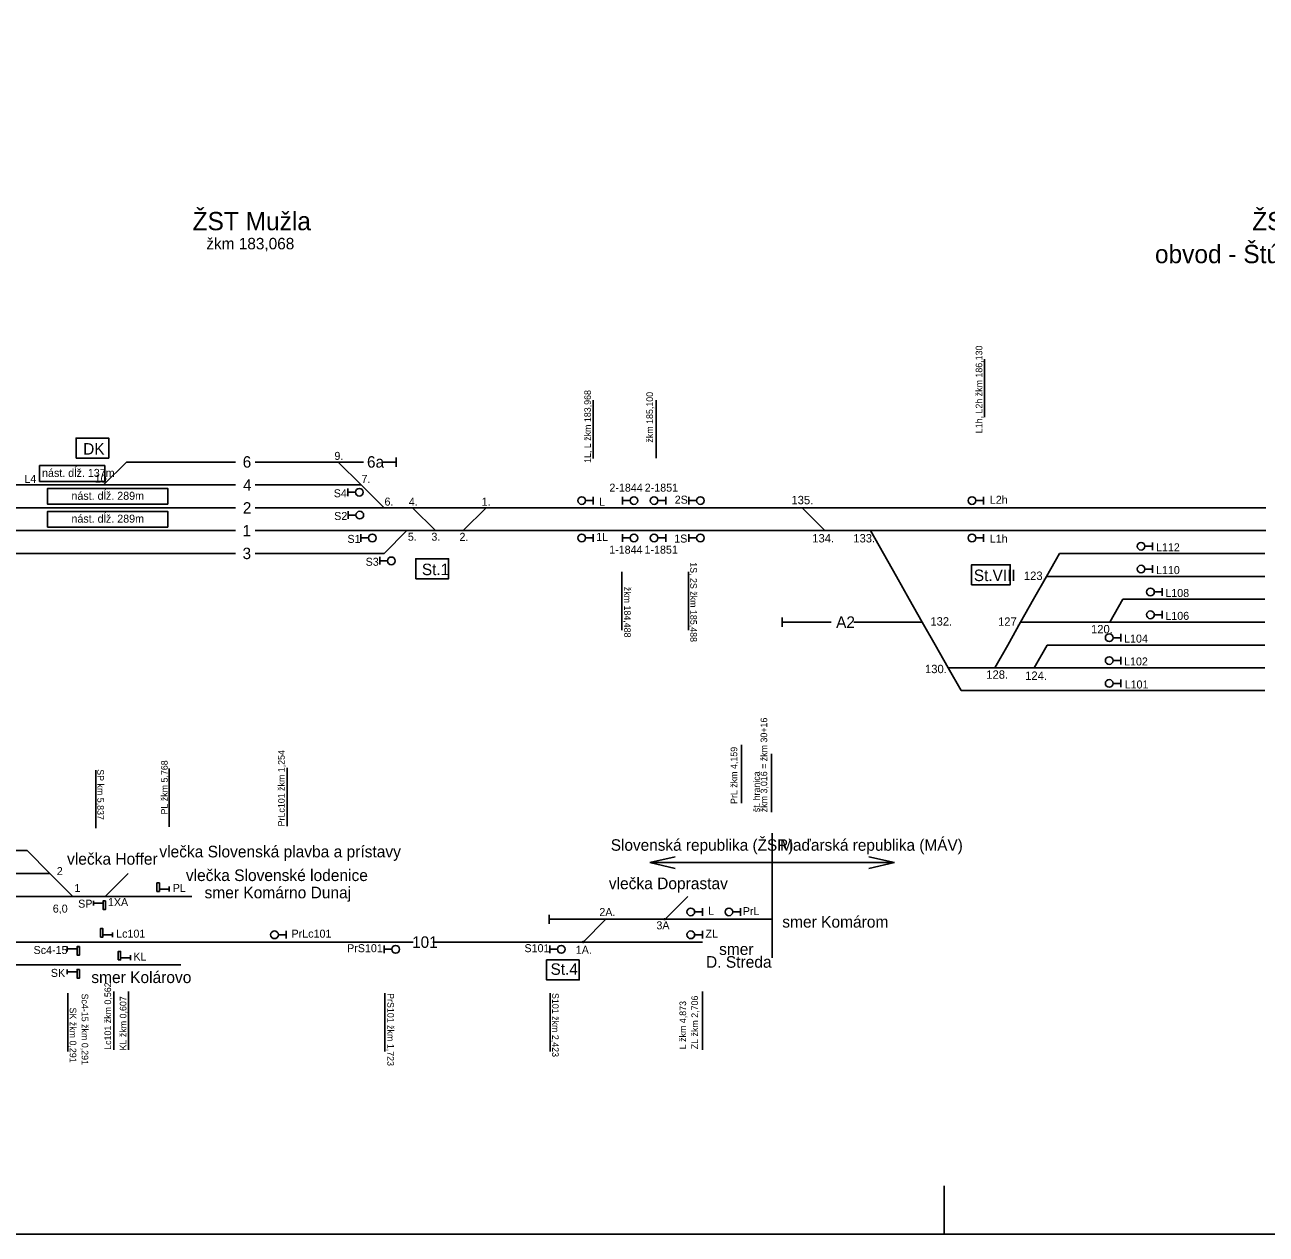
# Model space of a CAD drawing. Extents: x -119 to 851, y -238 to 59.
# Drawn here: x 390.6 to 499.2, y -238 to -132.3 of the extents above; entities that cross this region are included whole.
import ezdxf

# ---------------------------------------------------------------- set-up
doc = ezdxf.new("R2010")
doc.units = 0
for name, color, linetype in [('2', 7, 'Continuous'), ('budova', 7, 'Continuous'), ('Default', 7, 'Continuous'), ('Level 2', 7, 'Continuous'), ('nastupistia', 7, 'Continuous'), ('netlač', 7, 'Continuous'), ('popisky navestidla', 7, 'Continuous'), ('popisky stanic a zastavok', 7, 'Continuous'), ('PU_navestidla', 7, 'Continuous'), ('PU_oznacenie navestidiel', 7, 'Continuous'), ('PU_stan_kolaje', 7, 'Continuous'), ('PU_vlecky', 7, 'Continuous'), ('schema_km0-1_0-2', 7, 'Continuous'), ('schema_km1-0', 7, 'Continuous'), ('statna hranica', 7, 'Continuous')]:
    doc.layers.add(name, color=color, linetype=linetype)

msp = doc.modelspace()

# ---------------------------------------------------------------- linework, layer by layer
at = {"layer": '2'}
for p, q in [((402.64, -207.83), (403.26, -207.83)), ((403.26, -207.62), (403.26, -207.83)), ((403.26, -207.83), (403.26, -208.04)), ((396.63, -209.07), (396.63, -208.86)), ((396.63, -209.28), (396.63, -209.07)), ((397.25, -209.07), (396.63, -209.07)), ((398.31, -211.62), (398.31, -211.83)), ((397.69, -211.83), (398.31, -211.83)), ((398.31, -211.83), (398.31, -212.04)), ((394.35, -213.06), (394.35, -212.85)), ((394.98, -213.06), (394.35, -213.06)), ((394.35, -213.28), (394.35, -213.06)), ((399.25, -213.83), (399.87, -213.83)), ((399.87, -213.62), (399.87, -213.83)), ((399.87, -213.83), (399.87, -214.04)), ((394.35, -215.06), (394.35, -214.85)), ((394.35, -215.27), (394.35, -215.06)), ((394.98, -215.06), (394.35, -215.06))]:
    msp.add_line(p, q, dxfattribs=at)
for points in [[(402.19, -208.03), (402.4, -208.03), (402.4, -207.29), (402.19, -207.29)], [(402.19, -208.03), (402.4, -208.03), (402.4, -207.29), (402.19, -207.29)], [(397.69, -208.86), (397.48, -208.86), (397.48, -209.61), (397.69, -209.61)], [(397.69, -208.87), (397.48, -208.87), (397.48, -209.61), (397.69, -209.61)], [(397.25, -212.03), (397.46, -212.03), (397.46, -211.29), (397.25, -211.29)], [(397.25, -212.03), (397.46, -212.03), (397.46, -211.29), (397.25, -211.29)], [(395.42, -212.86), (395.21, -212.86), (395.21, -213.61), (395.42, -213.61)], [(395.42, -212.87), (395.21, -212.87), (395.21, -213.61), (395.42, -213.61)], [(398.8, -214.03), (399.01, -214.03), (399.01, -213.29), (398.8, -213.29)], [(398.8, -214.03), (399.01, -214.03), (399.01, -213.29), (398.8, -213.29)], [(395.42, -214.86), (395.21, -214.86), (395.21, -215.61), (395.42, -215.61)], [(395.42, -214.87), (395.21, -214.87), (395.21, -215.61), (395.42, -215.61)]]:
    msp.add_lwpolyline(points, close=True, dxfattribs=at)
at = {"layer": 'budova'}
for points in [[(395.11, -170.14), (397.98, -170.14), (397.98, -168.39), (395.11, -168.39)], [(424.82, -180.7), (427.69, -180.7), (427.69, -178.95), (424.82, -178.95)], [(473.44, -181.22), (476.82, -181.22), (476.82, -179.47), (473.44, -179.47)], [(439.12, -214.02), (436.26, -214.02), (436.26, -215.77), (439.12, -215.77)]]:
    msp.add_lwpolyline(points, close=True, dxfattribs=at)
at = {"layer": 'Default'}
for p, q in [((445.29, -205.52), (447.51, -205.01)), ((466.68, -205.52), (464.46, -205.01)), ((455.99, -205.52), (445.29, -205.52)), ((445.29, -205.52), (447.51, -206.02)), ((455.99, -205.52), (466.68, -205.52)), ((466.68, -205.52), (464.46, -206.02)), ((402.19, -208.03), (402.19, -207.29)), ((402.4, -207.29), (402.4, -208.03)), ((397.48, -209.61), (397.48, -208.86)), ((397.69, -208.86), (397.69, -209.61)), ((397.69, -209.61), (397.48, -209.61)), ((397.25, -212.03), (397.25, -211.29)), ((397.46, -211.29), (397.46, -212.03)), ((395.21, -213.61), (395.21, -212.86)), ((395.42, -213.61), (395.21, -213.61)), ((395.42, -212.86), (395.42, -213.61)), ((398.8, -214.03), (398.8, -213.29)), ((398.8, -213.29), (399.01, -213.29)), ((399.01, -213.29), (399.01, -214.03)), ((395.21, -215.61), (395.21, -214.86)), ((395.42, -214.86), (395.42, -215.61)), ((395.42, -215.61), (395.21, -215.61))]:
    msp.add_line(p, q, dxfattribs=at)
for points in [[(402.64, -207.83), (402.4, -207.83)], [(397.25, -209.07), (397.48, -209.07)], [(397.69, -211.83), (397.46, -211.83)], [(394.98, -213.06), (395.21, -213.06)], [(399.25, -213.83), (399.01, -213.83)], [(394.98, -215.06), (395.21, -215.06)]]:
    msp.add_lwpolyline(points, dxfattribs=at)
at = {"layer": 'Level 2'}
for p, q in [((423.12, -170.9), (423.12, -170.1)), ((409.05, -170.5), (399.52, -170.5)), ((418.05, -170.5), (410.78, -170.5)), ((420.25, -170.5), (418.05, -170.5)), ((423.12, -170.5), (421.98, -170.5)), ((388.2, -172.49), (409.05, -172.49)), ((410.78, -172.49), (420.05, -172.49)), ((377.88, -174.49), (394.08, -174.49)), ((394.08, -174.49), (409.05, -174.49)), ((410.78, -174.49), (417.67, -174.49)), ((417.67, -174.49), (440.34, -174.49)), ((371.76, -176.49), (392.88, -176.49)), ((392.88, -176.49), (409.05, -176.49)), ((410.78, -176.49), (418.67, -176.49)), ((418.67, -176.49), (436.97, -176.49)), ((436.97, -176.49), (440.34, -176.49)), ((388.73, -178.49), (409.05, -178.49)), ((410.78, -178.49), (422.05, -178.49)), ((456.87, -184.89), (456.87, -184.09)), ((390.83, -204.47), (386.03, -204.47)), ((392.83, -206.47), (386.03, -206.47)), ((405.25, -208.47), (362.23, -208.47)), ((436.5, -210.07), (436.5, -210.87)), ((436.5, -210.47), (441.46, -210.47)), ((449.89, -210.47), (441.46, -210.47)), ((424.6, -212.46), (387.27, -212.46)), ((449.89, -212.46), (426.32, -212.46)), ((404.28, -214.46), (386.78, -214.46))]:
    msp.add_line(p, q, dxfattribs=at)
for points in [[(490.07, -182.49), (490.47, -182.49)], [(456.87, -184.49), (461.14, -184.49)], [(463.14, -184.49), (469.12, -184.49)]]:
    msp.add_lwpolyline(points, dxfattribs=at)
at = {"layer": 'nastupistia'}
for points in [[(397.62, -172.18), (391.92, -172.18), (391.92, -170.8), (397.62, -170.8)], [(403.14, -174.18), (392.63, -174.18), (392.63, -172.8), (403.14, -172.8)], [(403.14, -176.18), (392.63, -176.18), (392.63, -174.8), (403.14, -174.8)]]:
    msp.add_lwpolyline(points, close=True, dxfattribs=at)
at = {"layer": 'netlač'}
for p, q in [((448.71, -174.49), (440.34, -174.49)), ((448.71, -174.49), (499.17, -174.49)), ((448.71, -176.49), (440.34, -176.49)), ((499.17, -176.49), (448.71, -176.49)), ((481.11, -178.49), (499.07, -178.49)), ((479.98, -180.49), (499.07, -180.49)), ((486.65, -182.49), (499.07, -182.49)), ((477.72, -184.49), (499.07, -184.49)), ((480.03, -186.49), (499.07, -186.49)), ((471.38, -188.48), (499.07, -188.48)), ((472.51, -190.48), (499.07, -190.48)), ((449.89, -210.47), (455.99, -210.47))]:
    msp.add_line(p, q, dxfattribs=at)
at = {"layer": 'popisky navestidla'}
for p, q in [((474.57, -161.48), (474.57, -166.57)), ((440.34, -170.18), (440.34, -165.09)), ((445.85, -165.07), (445.85, -170.16)), ((442.86, -180.09), (442.86, -185.18)), ((448.68, -180.09), (448.68, -185.18)), ((453.31, -195.23), (453.31, -200.32)), ((455.93, -196.01), (455.93, -201.1)), ((396.83, -202.51), (396.83, -197.42)), ((403.27, -197.29), (403.27, -202.38)), ((413.58, -197.23), (413.58, -202.32)), ((394.4, -222.03), (394.4, -216.94)), ((398.42, -216.79), (398.42, -221.88)), ((399.71, -216.79), (399.71, -221.88)), ((422.11, -222.03), (422.11, -216.94)), ((436.57, -222.03), (436.57, -216.94)), ((449.89, -221.89), (449.89, -216.8)), ((471.05, -238.01), (471.05, -233.77))]:
    msp.add_line(p, q, dxfattribs=at)
msp.add_lwpolyline([(-118.95, -238.01), (851.05, -238.01), (851.05, 58.99), (-118.95, 58.99)], close=True, dxfattribs=at)
at = {"layer": 'PU_navestidla'}
for p, q in [((418.88, -173.47), (418.88, -172.79)), ((418.88, -173.13), (419.56, -173.13)), ((440.34, -173.52), (440.34, -174.19)), ((442.89, -173.52), (442.89, -174.19)), ((446.68, -173.52), (446.68, -174.19)), ((448.71, -173.52), (448.71, -174.19)), ((474.48, -173.52), (474.48, -174.19)), ((440.34, -173.86), (439.67, -173.86)), ((442.89, -173.86), (443.56, -173.86)), ((446.68, -173.86), (446.01, -173.86)), ((448.71, -173.86), (449.38, -173.86)), ((474.48, -173.86), (473.81, -173.86)), ((418.92, -175.47), (418.92, -174.79)), ((418.92, -175.13), (419.59, -175.13)), ((420.02, -177.46), (420.02, -176.79)), ((440.34, -177.46), (440.34, -176.79)), ((442.89, -177.46), (442.89, -176.79)), ((446.68, -177.46), (446.68, -176.79)), ((448.71, -177.46), (448.71, -176.79)), ((474.48, -177.46), (474.48, -176.79)), ((420.02, -177.13), (420.7, -177.13)), ((440.34, -177.13), (439.67, -177.13)), ((442.89, -177.13), (443.56, -177.13)), ((446.68, -177.13), (446.01, -177.13)), ((448.71, -177.13), (449.38, -177.13)), ((474.48, -177.13), (473.81, -177.13)), ((489.27, -177.85), (488.6, -177.85)), ((489.27, -177.52), (489.27, -178.19)), ((421.68, -179.46), (421.68, -178.79)), ((421.68, -179.13), (422.35, -179.13)), ((489.27, -179.85), (488.6, -179.85)), ((489.27, -179.52), (489.27, -180.19)), ((490.09, -181.85), (489.41, -181.85)), ((490.09, -181.51), (490.09, -182.19)), ((490.09, -183.85), (489.41, -183.85)), ((490.09, -183.51), (490.09, -184.18)), ((486.48, -185.51), (486.48, -186.18)), ((486.48, -185.85), (485.8, -185.85)), ((486.48, -187.51), (486.48, -188.18)), ((486.48, -187.85), (485.8, -187.85)), ((486.48, -189.85), (485.8, -189.85)), ((486.48, -189.51), (486.48, -190.18)), ((449.89, -209.49), (449.89, -210.17)), ((453.22, -209.49), (453.22, -210.17)), ((449.89, -209.83), (449.22, -209.83)), ((453.22, -209.83), (452.54, -209.83)), ((413.48, -211.49), (413.48, -212.16)), ((449.89, -211.49), (449.89, -212.16)), ((413.48, -211.83), (412.81, -211.83)), ((422.06, -213.44), (422.06, -212.76)), ((436.54, -213.44), (436.54, -212.76)), ((449.89, -211.83), (449.22, -211.83)), ((422.06, -213.1), (422.73, -213.1)), ((436.54, -213.1), (437.21, -213.1))]:
    msp.add_line(p, q, dxfattribs=at)
for centre in [(419.89, -173.13), (439.34, -173.86), (443.9, -173.86), (445.67, -173.86), (449.72, -173.86), (473.47, -173.86), (419.93, -175.13), (421.03, -177.13), (439.34, -177.13), (443.9, -177.13), (445.67, -177.13), (449.72, -177.13), (473.47, -177.13), (488.26, -177.85), (422.69, -179.13), (488.26, -179.85), (489.08, -181.85), (489.08, -183.85), (485.47, -185.85), (485.47, -187.85), (485.47, -189.85), (448.88, -209.83), (452.21, -209.83), (412.47, -211.83), (448.88, -211.83), (423.07, -213.1), (437.55, -213.1)]:
    msp.add_circle(centre, 0.336, dxfattribs=at)
at = {"layer": 'PU_stan_kolaje'}
for points in [[(399.52, -170.5), (397.52, -172.49)], [(418.05, -170.5), (420.05, -172.49)], [(420.05, -172.49), (422.05, -174.49)], [(424.54, -174.49), (426.54, -176.49)], [(430.98, -174.49), (428.98, -176.49)], [(458.61, -174.49), (460.61, -176.49)], [(424.05, -176.49), (422.05, -178.49)], [(464.6, -176.49), (465.73, -178.49)], [(465.73, -178.49), (466.86, -180.49)], [(479.98, -180.49), (481.11, -178.49)], [(466.86, -180.49), (467.99, -182.49)], [(478.85, -182.49), (479.98, -180.49)], [(467.99, -182.49), (469.12, -184.49)], [(477.72, -184.49), (478.85, -182.49)], [(485.52, -184.49), (486.65, -182.49)], [(469.12, -184.49), (470.25, -186.48)], [(476.59, -186.49), (477.72, -184.49)], [(470.25, -186.48), (471.38, -188.48)], [(475.46, -188.48), (476.59, -186.49)], [(478.9, -188.48), (480.03, -186.49)], [(471.38, -188.48), (472.51, -190.48)], [(392.83, -206.47), (390.83, -204.47)], [(394.83, -208.47), (392.83, -206.47)], [(397.67, -208.47), (399.67, -206.47)], [(446.63, -210.47), (448.63, -208.47)], [(439.46, -212.46), (441.46, -210.47)]]:
    msp.add_lwpolyline(points, dxfattribs=at)
at = {"layer": 'schema_km0-1_0-2'}
for centre in [(446.58, -210.47), (439.46, -212.46)]:
    msp.add_circle(centre, 0.0502, dxfattribs=at)
at = {"layer": 'statna hranica'}
msp.add_line((455.99, -213.83), (455.99, -202.95), dxfattribs=at)

# ---------------------------------------------------------------- texts
at = {"layer": 'budova'}
for s, p in [('DK', (395.74, -169.84)), ('St.1', (425.36, -180.38)), ('St.VIII', (473.63, -180.9)), ('St.4', (436.61, -215.33))]:
    msp.add_text(s, height=1.004, dxfattribs=at).set_placement(p)
at = {"layer": 'Default'}
for s, p in [('Slovenská republika (ŽSR)', (441.88, -204.48)), ('Maďarská republika (MÁV)', (456.69, -204.48))]:
    msp.add_text(s, height=1.0044, dxfattribs=at).set_placement(p)
at = {"layer": 'Level 2'}
for s, height, p in [('135.', 0.733, (457.68, -174.18)), ('134.', 0.733, (459.5, -177.52)), ('133.', 0.733, (463.09, -177.52)), ('123.', 0.733, (478.01, -180.8)), ('A2', 1.004, (461.59, -184.99)), ('132.', 0.733, (469.83, -184.79)), ('127.', 0.733, (475.75, -184.81)), ('120.', 0.733, (483.88, -185.47)), ('130.', 0.733, (469.36, -188.95)), ('128.', 0.733, (474.72, -189.44)), ('124.', 0.733, (478.12, -189.54))]:
    msp.add_text(s, height=height, dxfattribs=at).set_placement(p)
at = {"layer": 'nastupistia'}
for s, p in [('nást. dĺž. 137m', (392.14, -171.79)), ('nást. dĺž. 289m', (394.71, -173.79)), ('nást. dĺž. 289m', (394.71, -175.79))]:
    msp.add_text(s, height=0.7, dxfattribs=at).set_placement(p)
at = {"layer": 'popisky navestidla'}
for s, rotation, p in [('L1h, L2h žkm 186,130', 90, (474.37, -167.97)), ('1L, L žkm 183,968', 90, (440.14, -170.57)), ('žkm 185,100', 90, (445.57, -168.79)), ('1S, 2S žkm 185,488 ', 270, (448.83, -179.25)), ('žkm 184,488', 270, (443.05, -181.4)), ('žkm 3,016 = žkm 30+16', 90, (455.56, -201.11)), ('PrLc101 žkm 1,254', 90, (413.36, -202.35)), ('PrL žkm 4,159', 90, (452.94, -200.39)), ('SP km 5,837', 270, (396.97, -197.35)), ('PL žkm 5,768', 90, (403.13, -201.31)), ('št. hranica ', 90, (454.92, -201.11)), ('Lc101 žkm 0,562', 90, (398.18, -221.89)), ('Sc4-15 žkm 0,291', 270, (395.6, -216.97)), ('PrS101 žkm 1,723', 270, (422.34, -216.93)), ('S101 žkm 2,423', 270, (436.75, -216.92)), ('KL žkm 0,607', 90, (399.52, -221.94)), ('L žkm 4,873', 90, (448.47, -221.84)), ('ZL žkm 2,706', 90, (449.51, -221.84)), ('SK žkm 0,291', 270, (394.56, -218.19))]:
    msp.add_text(s, height=0.5793, rotation=rotation, dxfattribs=at).set_placement(p)
at = {"layer": 'popisky stanic a zastavok'}
for s, height, p in [('ŽST Mužla', 1.6, (405.31, -150.22)), ('ŽST Štúrovo', 1.6, (497.98, -150.22)), ('žkm 183,068', 1.0044, (406.51, -151.89)), ('obvod - Štúrovo tranzitná skupina', 1.6, (489.47, -153.1))]:
    msp.add_text(s, height=height, dxfattribs=at).set_placement(p)
at = {"layer": 'PU_oznacenie navestidiel'}
for s, p in [('9.', (417.71, -170.3)), ('L4', (390.59, -172.31)), ('10', (396.75, -172.3)), ('7.', (420.08, -172.31)), ('2-1844', (441.76, -173.08)), ('2-1851', (444.85, -173.08)), ('S4', (417.65, -173.57)), ('6.', (422.09, -174.3)), ('4.', (424.22, -174.31)), ('1.', (430.58, -174.31)), ('L', (440.86, -174.31)), ('2S', (447.47, -174.13)), ('L2h', (475.03, -174.14)), ('S2', (417.69, -175.56)), ('S1', (418.85, -177.56)), ('5.', (424.13, -177.37)), ('3.', (426.19, -177.37)), ('2.', (428.65, -177.38)), ('1L', (440.61, -177.38)), ('1S', (447.43, -177.53)), ('L1h', (475.03, -177.54)), ('1-1844', (441.74, -178.5)), ('1-1851', (444.83, -178.5)), ('L112', (489.56, -178.3)), ('S3', (420.44, -179.56)), ('L110', (489.56, -180.29)), ('L108', (490.38, -182.29)), ('L106', (490.38, -184.29)), ('L104', (486.77, -186.28)), ('L102', (486.77, -188.28)), ('L101', (486.82, -190.29)), ('2', (393.43, -206.61)), ('1', (394.97, -208.09)), ('PL', (403.57, -208.08)), ('SP', (395.3, -209.46)), ('1XA', (397.9, -209.32)), ('2A.', (440.88, -210.19)), ('L', (450.4, -210.08)), ('PrL', (453.43, -210.11)), ('Lc101', (398.62, -212.08)), ('PrLc101', (413.96, -212.08)), ('3A', (445.87, -211.35)), ('ZL', (450.16, -212.08)), ('PrS101', (418.82, -213.35)), ('S101', (434.33, -213.35)), ('1A.', (438.82, -213.49)), ('Sc4-15', (391.4, -213.51)), ('KL', (400.13, -214.08)), ('SK', (392.91, -215.51))]:
    msp.add_text(s, height=0.7, dxfattribs=at).set_placement(p)
at = {"layer": 'PU_stan_kolaje'}
for s, height, p in [('6', 1, (409.69, -170.98)), ('6a', 1.004, (420.56, -170.98)), ('4', 1, (409.72, -173)), ('2', 1, (409.7, -175)), ('1', 1, (409.68, -176.99)), ('3', 1, (409.68, -178.98)), ('101', 1.004, (424.5, -212.97))]:
    msp.add_text(s, height=height, dxfattribs=at).set_placement(p)
at = {"layer": 'PU_vlecky'}
for s, p in [('vlečka Slovenská plavba a prístavy', (402.4, -205.06)), ('vlečka Hoffer', (394.33, -205.7)), ('vlečka Slovenské lodenice', (404.72, -207.13)), ('vlečka Doprastav', (441.71, -207.84)), ('smer Komárno Dunaj', (406.35, -208.64)), ('smer Komárom', (456.88, -211.2)), ('D. Streda', (450.21, -214.71)), ('smer ', (451.35, -213.59)), ('smer Kolárovo', (396.45, -216.05))]:
    msp.add_text(s, height=1.015, dxfattribs=at).set_placement(p)
at = {"layer": 'schema_km1-0'}
msp.add_text('6,0', height=0.7, dxfattribs=at).set_placement((393.08, -209.89))

doc.saveas('drawing.dxf')
